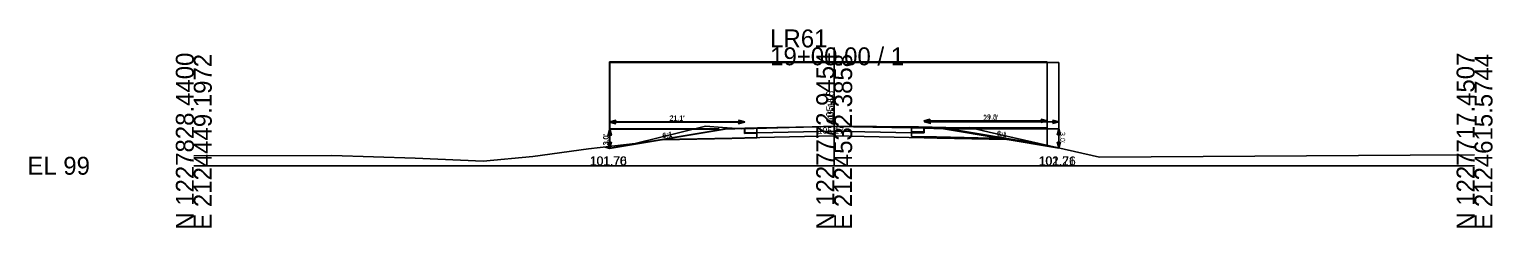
# Model space of a CAD drawing. Extents: x 2126751 to 2128979, y 1225108 to 1234639.
# Drawn here: x 2127750.9 to 2127979.4, y 1234107.5 to 1234138.6 of the extents above; entities that cross this region are included whole.
import ezdxf

# ---------------------------------------------------------------- set-up
doc = ezdxf.new("R2010")
doc.units = 0
for name, color, linetype in [('XS_CELL', 7, 'Continuous'), ('XS_M_DITCH', 7, 'Continuous'), ('XS_P_FINISHED_GRADE', 7, 'Continuous'), ('XS_P_FINISHED_GRADE_ELEV_TX', 7, 'Continuous'), ('XS_P_SUBGRADE_GRANULAR', 7, 'Continuous'), ('XS_P_SUBGRADE_PAVEMENT', 7, 'Continuous'), ('XS_P_TX_CLEARZONE', 7, 'Continuous'), ('XS_P_TX_DCH', 7, 'Continuous'), ('XS_P_TX_FS_BS', 7, 'Continuous'), ('XS_X_GROUND', 7, 'Continuous'), ('XS_X_GROUND_TX', 7, 'Continuous')]:
    doc.layers.add(name, color=color, linetype=linetype)

msp = doc.modelspace()

# ---------------------------------------------------------------- linework, layer by layer
at = {"layer": 'XS_CELL'}
for p, q in [((2127876.61, 1234117.21), (2127876.61, 1234135.72)), ((2127776.61, 1234117.21), (2127876.61, 1234117.21)), ((2127876.61, 1234117.21), (2127976.61, 1234117.21))]:
    msp.add_line(p, q, dxfattribs=at)
at = {"layer": 'XS_M_DITCH'}
for p, q in [((2127841.52, 1234119.91), (2127841.52, 1234133.47)), ((2127841.52, 1234133.47), (2127909.89, 1234133.47)), ((2127841.58, 1234119.97), (2127841.58, 1234133.37)), ((2127841.58, 1234133.37), (2127911.68, 1234133.37)), ((2127909.89, 1234133.47), (2127909.89, 1234120.41)), ((2127911.68, 1234133.37), (2127911.68, 1234119.97))]:
    msp.add_line(p, q, dxfattribs=at)
at = {"layer": 'XS_P_FINISHED_GRADE'}
for p, q in [((2127859.6, 1234122.91), (2127841.52, 1234119.91)), ((2127859.66, 1234122.97), (2127841.58, 1234119.97)), ((2127862.61, 1234123.03), (2127859.6, 1234122.91)), ((2127862.67, 1234123.09), (2127859.66, 1234122.97)), ((2127864.61, 1234123.07), (2127862.61, 1234123.03)), ((2127864.61, 1234123.13), (2127862.67, 1234123.09)), ((2127864.61, 1234123.07), (2127876.61, 1234123.37)), ((2127864.61, 1234123.13), (2127876.61, 1234123.37)), ((2127876.61, 1234123.37), (2127888.68, 1234123.29)), ((2127876.61, 1234123.37), (2127888.61, 1234123.13)), ((2127888.61, 1234123.13), (2127890.68, 1234123.09)), ((2127888.68, 1234123.29), (2127890.61, 1234123.25)), ((2127890.61, 1234123.25), (2127893.61, 1234123.13)), ((2127890.68, 1234123.09), (2127893.68, 1234122.97)), ((2127893.61, 1234123.13), (2127909.89, 1234120.41)), ((2127893.68, 1234122.97), (2127911.68, 1234119.97)), ((2127841.52, 1234119.91), (2127840.84, 1234120.13)), ((2127841.58, 1234119.97), (2127841.03, 1234120.15)), ((2127911.68, 1234119.97), (2127911.76, 1234119.99))]:
    msp.add_line(p, q, dxfattribs=at)
at = {"layer": 'XS_P_SUBGRADE_GRANULAR'}
for p, q in [((2127876.61, 1234121.87), (2127862.67, 1234121.59)), ((2127864.52, 1234121.57), (2127864.52, 1234122.32)), ((2127876.61, 1234121.87), (2127890.68, 1234121.59)), ((2127888.68, 1234121.79), (2127888.68, 1234122.54)), ((2127888.68, 1234121.79), (2127890.61, 1234121.75)), ((2127890.61, 1234121.75), (2127892.61, 1234121.71)), ((2127860.61, 1234121.49), (2127849.73, 1234121.27)), ((2127860.67, 1234121.55), (2127849.79, 1234121.33)), ((2127862.61, 1234121.53), (2127860.61, 1234121.49)), ((2127862.67, 1234121.59), (2127860.67, 1234121.55)), ((2127864.52, 1234121.57), (2127862.61, 1234121.53)), ((2127890.68, 1234121.59), (2127892.68, 1234121.55)), ((2127892.61, 1234121.71), (2127903.43, 1234121.49)), ((2127892.68, 1234121.55), (2127903.5, 1234121.33))]:
    msp.add_line(p, q, dxfattribs=at)
at = {"layer": 'XS_P_SUBGRADE_PAVEMENT'}
for p, q in [((2127862.61, 1234122.28), (2127862.61, 1234123.03)), ((2127864.52, 1234122.32), (2127862.61, 1234122.28)), ((2127862.67, 1234122.34), (2127862.67, 1234123.09)), ((2127864.61, 1234122.38), (2127862.67, 1234122.34)), ((2127864.52, 1234122.32), (2127864.52, 1234123.07)), ((2127864.61, 1234122.38), (2127876.61, 1234122.62)), ((2127876.61, 1234122.62), (2127888.61, 1234122.38)), ((2127888.61, 1234122.38), (2127890.68, 1234122.34)), ((2127888.68, 1234122.54), (2127888.68, 1234123.29)), ((2127888.68, 1234122.54), (2127890.61, 1234122.5)), ((2127890.61, 1234122.5), (2127890.61, 1234123.25)), ((2127890.68, 1234122.34), (2127890.68, 1234123.09))]:
    msp.add_line(p, q, dxfattribs=at)
at = {"layer": 'XS_P_TX_CLEARZONE'}
for p, q in [((2127841.52, 1234124.03), (2127842.52, 1234124.28)), ((2127841.52, 1234124.03), (2127842.52, 1234123.78)), ((2127862.61, 1234124.03), (2127841.52, 1234124.03)), ((2127841.58, 1234124.09), (2127842.58, 1234124.34)), ((2127841.58, 1234124.09), (2127842.58, 1234123.84)), ((2127862.67, 1234124.09), (2127841.58, 1234124.09)), ((2127862.61, 1234124.03), (2127861.61, 1234124.28)), ((2127862.61, 1234124.03), (2127861.61, 1234123.78)), ((2127862.67, 1234124.09), (2127861.67, 1234124.34)), ((2127862.67, 1234124.09), (2127861.67, 1234123.84)), ((2127890.61, 1234124.25), (2127891.61, 1234124.5)), ((2127890.61, 1234124.25), (2127891.61, 1234124)), ((2127890.61, 1234124.25), (2127909.89, 1234124.25)), ((2127890.68, 1234124.09), (2127891.68, 1234124.34)), ((2127890.68, 1234124.09), (2127891.68, 1234123.84)), ((2127890.68, 1234124.09), (2127911.68, 1234124.09)), ((2127909.89, 1234124.25), (2127908.89, 1234124.5)), ((2127909.89, 1234124.25), (2127908.89, 1234124)), ((2127911.68, 1234124.09), (2127910.68, 1234124.34)), ((2127911.68, 1234124.09), (2127910.68, 1234123.84)), ((2127841.52, 1234122.91), (2127841.27, 1234121.91)), ((2127841.58, 1234122.97), (2127841.33, 1234121.97)), ((2127841.52, 1234122.91), (2127841.77, 1234121.91)), ((2127841.52, 1234122.91), (2127841.52, 1234119.91)), ((2127858.59, 1234122.91), (2127841.52, 1234122.91)), ((2127841.58, 1234122.97), (2127841.83, 1234121.97)), ((2127841.58, 1234122.97), (2127841.58, 1234119.97)), ((2127858.65, 1234122.97), (2127841.58, 1234122.97)), ((2127894.61, 1234123.13), (2127909.89, 1234123.13)), ((2127894.68, 1234122.97), (2127911.68, 1234122.97)), ((2127911.68, 1234122.97), (2127911.43, 1234121.97)), ((2127911.68, 1234122.97), (2127911.68, 1234119.97)), ((2127911.68, 1234122.97), (2127911.93, 1234121.97)), ((2127841.52, 1234119.91), (2127841.27, 1234120.91)), ((2127841.58, 1234119.97), (2127841.33, 1234120.97)), ((2127841.52, 1234119.91), (2127841.77, 1234120.91)), ((2127841.58, 1234119.97), (2127841.83, 1234120.97)), ((2127911.68, 1234119.97), (2127911.43, 1234120.97)), ((2127911.68, 1234119.97), (2127911.93, 1234120.97))]:
    msp.add_line(p, q, dxfattribs=at)
at = {"layer": 'XS_X_GROUND'}
for p, q in [((2127845.54, 1234120.67), (2127856.54, 1234123.38)), ((2127856.54, 1234123.38), (2127859.17, 1234123.21)), ((2127859.17, 1234123.21), (2127862.21, 1234123)), ((2127862.21, 1234123), (2127866.03, 1234123.11)), ((2127866.03, 1234123.11), (2127876.71, 1234123.38)), ((2127876.71, 1234123.38), (2127889.8, 1234123.28)), ((2127889.8, 1234123.28), (2127896.2, 1234123.15)), ((2127896.2, 1234123.15), (2127897.73, 1234123.2)), ((2127897.73, 1234123.2), (2127900.83, 1234122.45)), ((2127900.83, 1234122.45), (2127918.06, 1234118.58)), ((2127829.57, 1234118.67), (2127838.25, 1234119.84)), ((2127838.25, 1234119.84), (2127845.54, 1234120.67)), ((2127776.61, 1234118.78), (2127798.16, 1234118.84)), ((2127798.16, 1234118.84), (2127811.19, 1234118.38)), ((2127811.19, 1234118.38), (2127821.78, 1234117.94)), ((2127821.78, 1234117.94), (2127829.57, 1234118.67)), ((2127918.06, 1234118.58), (2127966.55, 1234118.89)), ((2127966.55, 1234118.89), (2127976.61, 1234118.9))]:
    msp.add_line(p, q, dxfattribs=at)

# ---------------------------------------------------------------- texts
at = {"layer": 'XS_CELL'}
for s, p in [('LR61', (2127866.61, 1234135.72)), ('19+00.00 / 1', (2127866.61, 1234132.92)), ('EL 99', (2127750.61, 1234115.81))]:
    msp.add_text(s, height=2.8, dxfattribs=at).set_placement(p)
for s, p in [('N 1227828.4400', (2127776.61, 1234107.21)), ('E 2124449.1972', (2127779.41, 1234107.21)), ('N 1227772.9454', (2127876.61, 1234107.21)), ('E 2124532.3858', (2127879.41, 1234107.21)), ('N 1227717.4507', (2127976.61, 1234107.21)), ('E 2124615.5744', (2127979.41, 1234107.21))]:
    msp.add_text(s, height=2.8, rotation=90, dxfattribs=at).set_placement(p)
at = {"layer": 'XS_P_FINISHED_GRADE_ELEV_TX'}
for height in [1.25, 1]:
    msp.add_text(' 105.16', height=height, rotation=90, dxfattribs=at).set_placement((2127876.61, 1234123.37))
at = {"layer": 'XS_P_TX_CLEARZONE'}
for s, p in [("21.1'", (2127850.86, 1234124.23)), ("21.1'", (2127850.93, 1234124.29)), ("19.3'", (2127899.86, 1234124.45)), ("21.0'", (2127899.9, 1234124.29))]:
    msp.add_text(s, height=0.8, dxfattribs=at).set_placement(p)
for rotation, p in [(90, (2127841.32, 1234120.38)), (90, (2127841.38, 1234120.45)), (270, (2127911.88, 1234122.49))]:
    msp.add_text("3.0'", height=0.8, rotation=rotation, dxfattribs=at).set_placement(p)
at = {"layer": 'XS_P_TX_DCH'}
for s, p in [('101.70', (2127838.45, 1234117.27)), ('101.76', (2127838.51, 1234117.27)), ('102.21', (2127908.54, 1234117.27)), ('101.76', (2127908.61, 1234117.27))]:
    msp.add_text(s, height=1.4, dxfattribs=at).set_placement(p)
at = {"layer": 'XS_P_TX_FS_BS'}
for rotation, p in [(9.4211, (2127849.83, 1234121.49)), (9.4207, (2127849.9, 1234121.55)), (350.5377, (2127901.95, 1234121.94)), (350.5377, (2127902.02, 1234121.78))]:
    msp.add_text('6:1', height=0.8, rotation=rotation, dxfattribs=at).set_placement(p)
at = {"layer": 'XS_X_GROUND_TX'}
msp.add_text('105.17', height=1, dxfattribs=at).set_placement((2127874.05, 1234122.21))

doc.saveas('drawing.dxf')
